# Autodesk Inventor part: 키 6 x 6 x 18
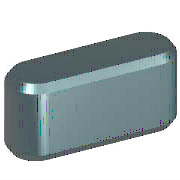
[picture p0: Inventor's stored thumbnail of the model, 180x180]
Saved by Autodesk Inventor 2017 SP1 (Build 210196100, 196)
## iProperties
IsCustomPart: 1
Created: 2012-02
Part Number: 키 6 x 6 x 18
Material: 강철, 연강
Description: 키 및 해당 키홈
Document SubType Name: Modeling
Standard: KS B 1311
Designer: mduedu
Standards Organization: KS
Language: ko-KR
Size Designation: 6 x 6 x 18
Categories: <MemberInstance><Categories><Category DisplayName="샤프트 부품" InternalName="7f7aeb1f-a693-4053-b835-cee3144e0d98" Mnemonic="SHFT"><Category DisplayName="키" Interna
Density: 1 g/cm^3
Appearance: 노란색
Author: mduedu
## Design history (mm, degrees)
workplane "Work Plane1"
workplane "Work Plane2"
sketch "스케치1"
  geometry: L1 (3, 3)-(15, 3); L2 (15, -3)-(3, -3); L3 (0, 9.4)-(0, -7.4) reference; L4 (-5, 0)-(30, 0) reference; L5 (18, 0)-(18, 7); A1 r 3 centre (3, 0) between (3, 3) and (3, -3); A2 r 3 centre (15, 0) between (15, -3) and (15, 3)
  constraints: 6 end point, 5 point on circle, 4 tangent, 3 point on line, 2 centre point, 1 horizontal, 1 parallel, 1 perpendicular
  dimensions: "d0" = 3 radius of A1 (= 0.5 x PB); "d13" = 3 radius of A2 (= 0.5 x PB); "d14" = 18 distance between parallel lines of L5 L3 (= NLG)
extrude "본체1" new body sketch "스케치1" taper "d3" = 0 deg; stored distance "d4" = 10
workplane "Work Plane3"
body "Solid1"
chamfer "모따기1" distance "d8" = 0.4 (= PHH); stored, may be unused: second distance "d9" = 0.4 (= PHH), angle "d15" = 45 deg
other parameters: "d1" = -3.5 (= -PNT), "d2" = 2.5 (= PH - PNT), "NLG" = 18 [user parameter; used in 3 equation terms], "PB" = 6 [user parameter; used in 2 equation terms], "PNT" = 3.5 [user parameter; used in 2 equation terms], "PH" = 6 [user parameter; used in 1 equation term], "PHH" = 0.4 [user parameter; used in 2 equation terms], "d10" = 0, "d16" = 0, "d17" = 0, "d18" = 0, "WDMIN" = 17 [user parameter], "PLB2" = 18 (= NLG) [user parameter], "WDMAX" = 22 [user parameter], "PLB1" = 18 (= NLG) [user parameter], "RR" = 0.16 [user parameter], "PUEB" = 2.8 [user parameter]
